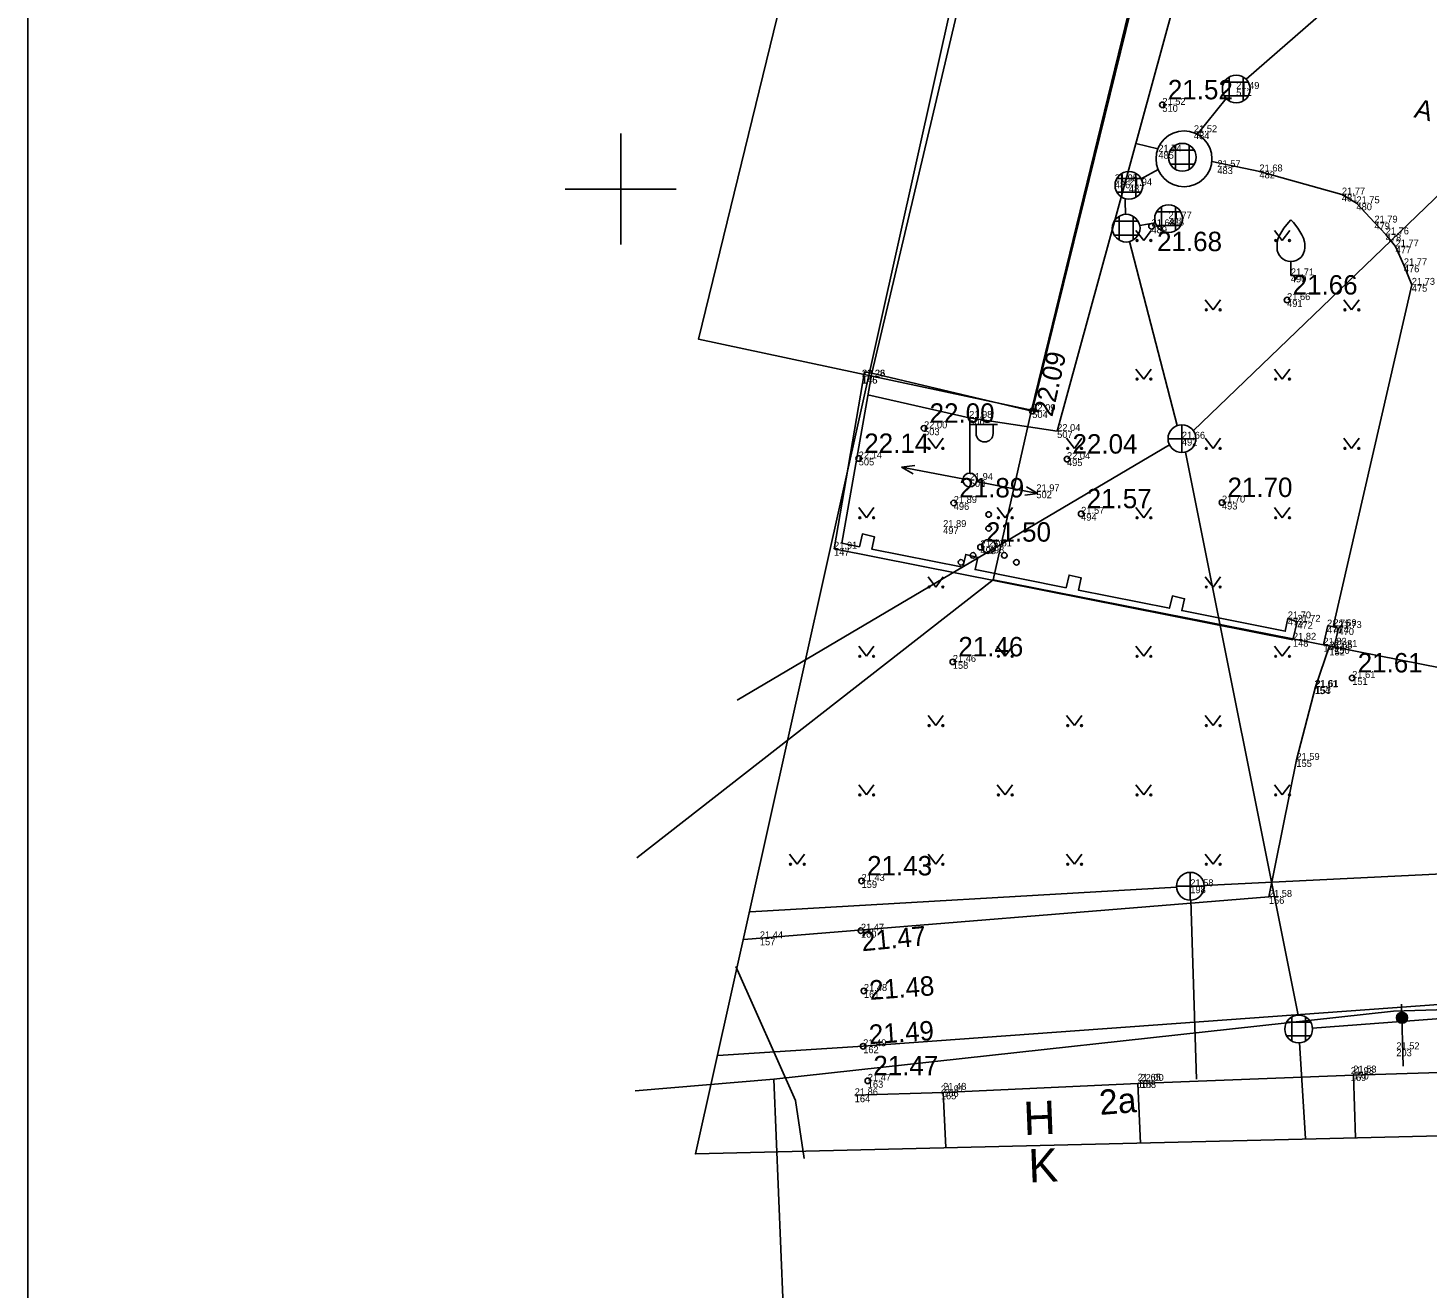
# Model space of a CAD drawing. Extents: x 714279 to 714471, y 6589851 to 6590083.
# Drawn here: x 714278.6 to 714329.1, y 6589960.4 to 6590005.8 of the extents above; entities that cross this region are included whole.
import ezdxf

# ---------------------------------------------------------------- set-up
doc = ezdxf.new("R2010")
doc.units = 0
for name, color, linetype in [('AED', 7, 'Continuous'), ('DKAEV', 7, 'Continuous'), ('DTRASS', 7, 'Continuous'), ('HALJASTUS', 7, 'Continuous'), ('HOONE', 7, 'Continuous'), ('KKAEV', 7, 'Continuous'), ('KORGUS', 7, 'Continuous'), ('KTRASS', 7, 'Continuous'), ('MOOTKORG', 7, 'Continuous'), ('MOOTMPUNKT', 7, 'Continuous'), ('MOOTPIIR', 7, 'Continuous'), ('MPKAABEL', 7, 'Continuous'), ('MPOHULIIN', 7, 'Continuous'), ('PIIR', 7, 'Continuous'), ('POST', 7, 'Continuous'), ('PUU', 7, 'Continuous'), ('RAJATISEDET', 7, 'Continuous'), ('SIOHULIIN', 7, 'Continuous'), ('SKKAEV', 7, 'Continuous'), ('SKTRASS', 7, 'Continuous'), ('TEE', 7, 'Continuous'), ('VORK', 7, 'Continuous'), ('VORMISTUS', 7, 'Continuous')]:
    doc.layers.add(name, color=color, linetype=linetype)

# ---------------------------------------------------------------- blocks, each defined once
blk = doc.blocks.new('RING02')
at = {"layer": 'KORGUS'}
blk.add_circle((0, 0), 0.2, dxfattribs=at)
blk = doc.blocks.new('RING02_2')
at = {"layer": 'KORGUS'}
blk.add_circle((0, 0), 0.2, dxfattribs=at)
blk = doc.blocks.new('RING02_1')
at = {"layer": 'KORGUS'}
blk.add_circle((0, 0), 0.2, dxfattribs=at)
blk = doc.blocks.new('KAKAEV')
at = {"layer": 'KKAEV'}
for p, q in [((-1, 0), (1, 0)), ((0, -1), (0, 1))]:
    blk.add_line(p, q, dxfattribs=at)
blk.add_circle((0, 0), 1, dxfattribs=at)
blk = doc.blocks.new('VILJA1')
at = {"layer": 'PUU'}
for p, q in [((0, 0), (0, 1)), ((0.8, 0), (0, 0))]:
    blk.add_line(p, q, dxfattribs=at)
for points in [[(-1, 2), (-1, 2.3), (-0.98, 2.43), (-0.91, 2.69), (-0.79, 2.93), (-0.5, 3.4), (-0.18, 3.81), (0, 4)], [(1, 2), (1, 2.3), (0.98, 2.43), (0.91, 2.69), (0.79, 2.93), (0.5, 3.4), (0.18, 3.81), (0, 4)]]:
    blk.add_lwpolyline(points, dxfattribs=at)
blk.add_arc((0, 2), 1, 180, 0, dxfattribs=at)
blk = doc.blocks.new('VQSA')
at = {"layer": 'HALJASTUS'}
for centre, radius in [((0, 2.3), 0.2), ((0, 1.3), 0.2), ((0, 0), 0.5), ((-2, -1.15), 0.2), ((-1.13, -0.65), 0.2), ((1.13, -0.65), 0.2), ((2, -1.15), 0.2)]:
    blk.add_circle(centre, radius, dxfattribs=at)
blk = doc.blocks.new('BEPOST')
at = {"layer": 'POST'}
for radius in [0.5, 0.0467]:
    blk.add_circle((0, 0), radius, dxfattribs=at)
blk = doc.blocks.new('POINT_DISPLAY')
blk.add_line((0, 0), (0, 0))
blk = doc.blocks.new('VAPOST')
at = {"layer": 'POST'}
for p, q in [((0, 0.5), (0, 4.5)), ((0, 4), (2, 4)), ((0.45, 3.36), (0.45, 4)), ((1.68, 3.36), (1.68, 4))]:
    blk.add_line(p, q, dxfattribs=at)
blk.add_arc((1.07, 3.36), 0.613, 180, 0, dxfattribs=at)
blk.add_blockref('POINT_DISPLAY', (0, 0), dxfattribs=at)
blk = doc.blocks.new('SISUUN')
at = {"layer": 'SIOHULIIN'}
blk.add_line((0.5, 0), (4.98, 0), dxfattribs=at)
for radius in [0.399, 0.38, 0.361, 0.342, 0.323, 0.304, 0.285, 0.266, 0.247, 0.228, 0.209, 0.191, 0.172, 0.153, 0.134, 0.115, 0.0959, 0.0769, 0.058, 0.0391, 0.0201, 0.00122]:
    blk.add_circle((3.99, 0), radius, dxfattribs=at)
blk.add_blockref('POINT_DISPLAY', (0, 0), dxfattribs=at)
blk = doc.blocks.new('MPSUUN')
at = {"layer": 'MPOHULIIN'}
for p, q in [((0.5, 0), (5, 0)), ((5, 0), (4.1, 0.3)), ((5, 0), (4.1, -0.3))]:
    blk.add_line(p, q, dxfattribs=at)
blk.add_blockref('POINT_DISPLAY', (0, 0), dxfattribs=at)
blk = doc.blocks.new('KAKAEV_1')
at = {"layer": 'SKKAEV'}
for p, q in [((-1, 0), (1, 0)), ((0, -1), (0, 1))]:
    blk.add_line(p, q, dxfattribs=at)
blk.add_circle((0, 0), 1, dxfattribs=at)
blk = doc.blocks.new('DRKAEV')
at = {"layer": 'DKAEV'}
for p, q in [((-0.87, 0.5), (0.87, 0.5)), ((-0.5, -0.87), (-0.5, 0.87)), ((0.5, 0.87), (0.5, -0.87)), ((0.87, -0.5), (-0.87, -0.5))]:
    blk.add_line(p, q, dxfattribs=at)
blk.add_circle((0, 0), 1, dxfattribs=at)
blk = doc.blocks.new('MURU_1')
at = {"layer": 'HALJASTUS'}
for p, q in [((-0.93, 1.21), (0, 0)), ((0, 0), (0.89, 1.21))]:
    blk.add_line(p, q, dxfattribs=at)
for centre in [(-0.8, 0), (0.86, 0)]:
    blk.add_circle(centre, 0.11, dxfattribs=at)

msp = doc.modelspace()

# ---------------------------------------------------------------- linework, layer by layer
at = {"layer": 'AED'}
for points in [[(714324.246, 6589983.744), (714324.403, 6589984.391), (714324.06, 6589984.514), (714323.969, 6589984.053), (714320.235, 6589984.794), (714320.337, 6589985.223), (714319.896, 6589985.328), (714319.79, 6589984.882), (714316.507, 6589985.534), (714316.612, 6589985.973), (714316.171, 6589986.078), (714316.062, 6589985.622), (714312.779, 6589986.273), (714312.885, 6589986.715), (714312.444, 6589986.82), (714312.334, 6589986.361), (714309.052, 6589987.012), (714309.157, 6589987.454), (714308.716, 6589987.559), (714308.607, 6589987.101), (714307.98, 6589987.225), (714309.058, 6589993.359), (714308.789, 6589993.405), (714307.695, 6589987.027), (714324.246, 6589983.744)], [(714325.888, 6589984.167), (714325.733, 6589983.485), (714325.349, 6589983.572), (714325.504, 6589984.254), (714325.888, 6589984.167)], [(714318.651, 6589967.739), (714326.425, 6589968.035)], [(714308.44, 6589967.315), (714311.635, 6589967.411)]]:
    msp.add_lwpolyline(points, dxfattribs=at)
at = {"layer": 'DTRASS'}
for points in [[(714328.331, 6590008.997), (714322.553, 6590003.965)], [(714321.838, 6590003.267), (714320.789, 6590001.966)], [(714319.39, 6590000.702), (714318.767, 6590000.375)], [(714318.193, 6589999.654), (714318.193, 6589999.561), (714318.205, 6589999.089)], [(714318.719, 6589998.692), (714319.281, 6589998.787)], [(714318.346, 6589998.104), (714320.074, 6589991.468)], [(714324.439, 6589970.203), (714320.365, 6589990.512)], [(714340.125, 6589970.88), (714324.95, 6589969.733)], [(714324.479, 6589969.204), (714324.695, 6589965.757)]]:
    msp.add_lwpolyline(points, dxfattribs=at)
at = {"layer": 'HOONE'}
for points in [[(714319.159, 6590036.112), (714325.33, 6590034.654), (714314.842, 6589991.992), (714309.058, 6589993.359), (714319.159, 6590036.112)], [(714326.496, 6589965.774), (714326.425, 6589968.035), (714339.231, 6589968.437), (714339.305, 6589966.095)], [(714311.727, 6589965.435), (714311.635, 6589967.411), (714318.651, 6589967.739), (714318.651, 6589967.739), (714318.752, 6589965.575)]]:
    msp.add_lwpolyline(points, dxfattribs=at)
at = {"layer": 'KORGUS'}
msp.add_circle((714314.842, 6589991.992), 0.1, dxfattribs=at)
at = {"layer": 'KTRASS'}
for points in [[(714321.04, 6589974.878), (714351.74, 6589976.38)], [(714304.668, 6589973.936), (714320.044, 6589974.823)], [(714320.559, 6589974.354), (714320.77, 6589967.891)]]:
    msp.add_lwpolyline(points, dxfattribs=at)
at = {"layer": 'MOOTPIIR'}
msp.add_lwpolyline([(714325.392, 6590064.148), (714418.405, 6590047.495), (714428.059, 6590039.059), (714392.952, 6589961.13), (714372.822, 6589966.903), (714302.696, 6589965.199), (714319.941, 6590042.637), (714325.392, 6590064.148)], dxfattribs=at)
at = {"layer": 'MPKAABEL'}
msp.add_lwpolyline([(714304.149, 6589971.964), (714306.307, 6589967.128), (714306.622, 6589965.036)], dxfattribs=at)
at = {"layer": 'PIIR'}
for points in [[(714331.191, 6590053.239), (714328.01, 6590040.642), (714325.217, 6590034.631), (714313.247, 6590037.362), (714302.809, 6589994.583), (714314.816, 6589992.023), (714325.215, 6590034.631)], [(714313.433, 6589985.9), (714378.228, 6589973.152), (714405.629, 6590034.791), (714332.408, 6590052.951), (714332.595, 6590052.951)], [(714314.816, 6589992.023), (714313.433, 6589985.9), (714300.583, 6589975.877)], [(714305.517, 6589967.896), (714327.878, 6589970.35), (714360.817, 6589971.365), (714377.13, 6589970.9), (714368.352, 6589950.974)], [(714300.523, 6589967.472), (714305.517, 6589967.896), (714305.864, 6589959.716), (714309.783, 6589950.981)]]:
    msp.add_lwpolyline(points, dxfattribs=at)
at = {"layer": 'RAJATISEDET'}
msp.add_circle((714320.316, 6590001.091), 1.008, dxfattribs=at)
at = {"layer": 'SKTRASS'}
for points in [[(714320.65, 6589991.283), (714354.787, 6590024.118)], [(714304.204, 6589981.56), (714319.79, 6589990.777)]]:
    msp.add_lwpolyline(points, dxfattribs=at)
at = {"layer": 'TEE'}
for points in [[(714308.915, 6589992.579), (714312.567, 6589991.748), (714315.741, 6589991.273), (714319.939, 6590006.608), (714326.841, 6590035.429), (714325.606, 6590035.884), (714319.931, 6590037.223), (714319.717, 6590036.149)], [(714319.374, 6590001.455), (714318.581, 6590001.648)], [(714323.053, 6590000.632), (714321.321, 6590000.993)], [(714325.7, 6589984.21), (714328.532, 6589996.547), (714328.246, 6589997.25), (714327.948, 6589997.931), (714327.592, 6589998.366), (714327.184, 6589998.792), (714326.536, 6589999.487), (714326.012, 6589999.804), (714323.037, 6590000.636)], [(714325.567, 6589983.523), (714325.055, 6589982.044)], [(714325.055, 6589982.044), (714324.371, 6589979.409), (714323.377, 6589974.469), (714304.436, 6589972.928)], [(714329.664, 6589970.604), (714308.745, 6589969.083), (714303.506, 6589968.747)]]:
    msp.add_lwpolyline(points, dxfattribs=at)
at = {"layer": 'VORK'}
for p, q in [((714300, 6590002), (714300, 6589998)), ((714298, 6590000), (714302, 6590000))]:
    msp.add_line(p, q, dxfattribs=at)
at = {"layer": 'VORMISTUS'}
msp.add_lwpolyline([(714471.122, 6589929.143), (714278.622, 6589929.143), (714278.622, 6590071.643), (714471.122, 6590071.643), (714471.122, 6589929.143)], dxfattribs=at)

# ---------------------------------------------------------------- block references
at = {"layer": 'DKAEV', "xscale": 0.5, "yscale": 0.5}
for p in [(714322.199, 6590003.611), (714320.258, 6590001.148), (714318.328, 6590000.136), (714319.759, 6589998.933), (714318.229, 6589998.59), (714324.45, 6589969.704)]:
    msp.add_blockref('DRKAEV', p, dxfattribs=at)
at = {"layer": 'HALJASTUS'}
for name, p, xscale, yscale in [('MURU_1', (714318.862, 6589998.147), 0.3, 0.3), ('MURU_1', (714323.862, 6589998.147), 0.3, 0.3), ('MURU_1', (714321.362, 6589995.647), 0.3, 0.3), ('MURU_1', (714326.362, 6589995.647), 0.3, 0.3), ('MURU_1', (714318.862, 6589993.147), 0.3, 0.3), ('MURU_1', (714323.862, 6589993.147), 0.3, 0.3), ('MURU_1', (714311.362, 6589990.647), 0.3, 0.3), ('MURU_1', (714316.362, 6589990.647), 0.3, 0.3), ('MURU_1', (714321.362, 6589990.647), 0.3, 0.3), ('MURU_1', (714326.362, 6589990.647), 0.3, 0.3), ('MURU_1', (714308.862, 6589988.147), 0.3, 0.3), ('VQSA', (714313.272, 6589987.113), 0.5, 0.5), ('MURU_1', (714313.862, 6589988.147), 0.3, 0.3), ('MURU_1', (714318.862, 6589988.147), 0.3, 0.3), ('MURU_1', (714323.862, 6589988.147), 0.3, 0.3), ('MURU_1', (714311.362, 6589985.647), 0.3, 0.3), ('MURU_1', (714321.362, 6589985.647), 0.3, 0.3), ('MURU_1', (714308.862, 6589983.147), 0.3, 0.3), ('MURU_1', (714313.862, 6589983.147), 0.3, 0.3), ('MURU_1', (714318.862, 6589983.147), 0.3, 0.3), ('MURU_1', (714323.862, 6589983.147), 0.3, 0.3), ('MURU_1', (714311.362, 6589980.647), 0.3, 0.3), ('MURU_1', (714316.362, 6589980.647), 0.3, 0.3), ('MURU_1', (714321.362, 6589980.647), 0.3, 0.3), ('MURU_1', (714308.862, 6589978.147), 0.3, 0.3), ('MURU_1', (714313.862, 6589978.147), 0.3, 0.3), ('MURU_1', (714318.862, 6589978.147), 0.3, 0.3), ('MURU_1', (714323.862, 6589978.147), 0.3, 0.3), ('MURU_1', (714306.362, 6589975.647), 0.3, 0.3), ('MURU_1', (714311.362, 6589975.647), 0.3, 0.3), ('MURU_1', (714316.362, 6589975.647), 0.3, 0.3), ('MURU_1', (714321.362, 6589975.647), 0.3, 0.3)]:
    msp.add_blockref(name, p, dxfattribs=dict(at, xscale=xscale, yscale=yscale))
at = {"layer": 'KKAEV', "xscale": 0.5, "yscale": 0.5}
for p in [(714320.24, 6589990.996), (714320.543, 6589974.854)]:
    msp.add_blockref('KAKAEV', p, dxfattribs=at)
at = {"layer": 'KORGUS', "xscale": 0.5, "yscale": 0.5}
for name, p in [('RING02', (714319.535, 6590003.037)), ('RING02_2', (714319.145, 6589998.658)), ('RING02', (714324.034, 6589995.996)), ('RING02', (714310.941, 6589991.372)), ('RING02_1', (714308.584, 6589990.283)), ('RING02', (714316.096, 6589990.259)), ('RING02', (714312.011, 6589988.678)), ('RING02', (714321.685, 6589988.693)), ('RING02', (714316.607, 6589988.288)), ('RING02', (714312.975, 6589987.083)), ('RING02', (714311.977, 6589982.946)), ('RING02', (714326.382, 6589982.366)), ('RING02', (714308.687, 6589975.045)), ('RING02_2', (714308.664, 6589973.251)), ('RING02_1', (714308.771, 6589971.078)), ('RING02_2', (714308.745, 6589969.083)), ('RING02', (714308.911, 6589967.836))]:
    msp.add_blockref(name, p, dxfattribs=at)
at = {"layer": 'MPOHULIIN', "xscale": 0.5, "yscale": 0.5}
for rotation in [169.47487191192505, -11.231766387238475]:
    msp.add_blockref('MPSUUN', (714312.59, 6589989.507), dxfattribs=dict(at, rotation=rotation))
at = {"layer": 'POST', "xscale": 0.5, "yscale": 0.5}
for name, p in [('VAPOST', (714312.59, 6589989.507)), ('BEPOST', (714312.589, 6589989.507))]:
    msp.add_blockref(name, p, dxfattribs=at)
at = {"layer": 'PUU', "xscale": 0.5, "yscale": 0.5}
msp.add_blockref('VILJA1', (714324.171, 6589996.886), dxfattribs=at)
at = {"layer": 'SIOHULIIN', "xscale": 0.49999999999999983, "yscale": 0.4999999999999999, "rotation": 91.40279018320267}
msp.add_blockref('SISUUN', (714328.226, 6589968.115), dxfattribs=at)
at = {"layer": 'SKKAEV', "xscale": 0.5, "yscale": 0.5}
msp.add_blockref('KAKAEV_1', (714320.24, 6589990.996), dxfattribs=at)

# ---------------------------------------------------------------- texts
at = {"layer": 'HOONE'}
for s, height, rotation, p in [('2a', 0.9, 4.4689, (714317.293, 6589966.604)), ('H', 1.2, 2.2992, (714314.547, 6589965.878)), ('K', 1.2, 2.2992, (714314.727, 6589964.166))]:
    msp.add_text(s, height=height, rotation=rotation, dxfattribs=at).set_placement(p)
at = {"layer": 'KORGUS'}
for s, p in [('21.52', (714319.735, 6590003.237)), ('21.68', (714319.345, 6589997.761)), ('21.66', (714324.234, 6589996.196)), ('22.00', (714311.141, 6589991.572)), ('22.14', (714308.784, 6589990.483)), ('22.04', (714316.296, 6589990.459)), ('21.89', (714312.211, 6589988.878)), ('21.70', (714321.885, 6589988.893)), ('21.57', (714316.807, 6589988.488)), ('21.50', (714313.175, 6589987.283)), ('21.46', (714312.177, 6589983.146)), ('21.61', (714326.582, 6589982.566)), ('21.43', (714308.887, 6589975.245)), ('21.47', (714309.111, 6589968.036))]:
    msp.add_text(s, height=0.7, dxfattribs=at).set_placement(p)
for s, rotation, p in [('22.09', 77.5872, (714315.567, 6589991.761)), ('21.47', 5.5012, (714308.711, 6589972.506)), ('21.48', 4.2186, (714308.996, 6589970.753)), ('21.49', 3.7117, (714308.978, 6589969.157))]:
    msp.add_text(s, height=0.7, rotation=rotation, dxfattribs=at).set_placement(p)
at = {"layer": 'MOOTKORG'}
for s, p in [('21.49', (714322.199, 6590003.611)), ('21.52', (714319.535, 6590003.037)), ('21.52', (714320.674, 6590002.051)), ('21.74', (714319.39, 6590001.346)), ('21.57', (714321.519, 6590000.791)), ('21.68', (714323.037, 6590000.636)), ('21.95', (714317.819, 6590000.28)), ('21.94', (714318.328, 6590000.136)), ('21.77', (714326.012, 6589999.804)), ('21.75', (714326.536, 6589999.487)), ('21.68', (714319.145, 6589998.658)), ('21.77', (714319.759, 6589998.933)), ('21.79', (714327.184, 6589998.792)), ('21.76', (714327.592, 6589998.366)), ('21.77', (714327.948, 6589997.931)), ('21.77', (714328.246, 6589997.25)), ('21.71', (714324.171, 6589996.886)), ('21.73', (714328.532, 6589996.547)), ('21.66', (714324.034, 6589995.996)), ('22.28', (714308.696, 6589993.232)), ('22.26', (714308.707, 6589993.236)), ('22.09', (714314.842, 6589991.992)), ('21.98', (714312.567, 6589991.748)), ('22.00', (714310.941, 6589991.372)), ('22.04', (714315.741, 6589991.273)), ('21.66', (714320.24, 6589990.996)), ('22.14', (714308.584, 6589990.283)), ('22.04', (714316.096, 6589990.259)), ('21.94', (714312.589, 6589989.507)), ('21.94', (714312.59, 6589989.507)), ('21.97', (714314.991, 6589989.1)), ('21.89', (714312.011, 6589988.678)), ('21.70', (714321.685, 6589988.693)), ('21.57', (714316.607, 6589988.288)), ('21.89', (714311.629, 6589987.809)), ('21.91', (714307.695, 6589987.027)), ('21.50', (714312.975, 6589987.083)), ('21.51', (714313.272, 6589987.113)), ('21.70', (714324.06, 6589984.514)), ('21.72', (714324.403, 6589984.391)), ('21.75', (714325.477, 6589984.221)), ('21.69', (714325.705, 6589984.234)), ('21.73', (714325.888, 6589984.167)), ('21.82', (714324.246, 6589983.744)), ('21.83', (714325.347, 6589983.563)), ('21.65', (714325.56, 6589983.428)), ('21.81', (714325.733, 6589983.485)), ('21.46', (714311.977, 6589982.946)), ('21.61', (714325.023, 6589982.033)), ('21.61', (714325.055, 6589982.044)), ('21.61', (714326.382, 6589982.366)), ('21.59', (714324.371, 6589979.409)), ('21.43', (714308.687, 6589975.045)), ('21.58', (714320.543, 6589974.854)), ('21.58', (714323.377, 6589974.469)), ('21.44', (714305.018, 6589972.975)), ('21.47', (714308.664, 6589973.251)), ('21.48', (714308.771, 6589971.078)), ('21.49', (714308.745, 6589969.083)), ('21.52', (714327.974, 6589968.972)), ('21.47', (714308.911, 6589967.836)), ('21.65', (714318.646, 6589967.839)), ('22.00', (714318.748, 6589967.83)), ('21.93', (714326.331, 6589968.081)), ('21.53', (714326.422, 6589968.135)), ('21.86', (714308.44, 6589967.315)), ('21.91', (714311.546, 6589967.419)), ('21.48', (714311.63, 6589967.511))]:
    msp.add_text(s, height=0.25, dxfattribs=at).set_placement(p)
at = {"layer": 'MOOTMPUNKT'}
for s, p in [('511', (714322.199, 6590003.361)), ('510', (714319.535, 6590002.787)), ('484', (714320.674, 6590001.801)), ('485', (714319.39, 6590001.096)), ('483', (714321.519, 6590000.541)), ('482', (714323.037, 6590000.386)), ('486', (714317.819, 6590000.03)), ('487', (714318.328, 6589999.886)), ('481', (714326.012, 6589999.554)), ('480', (714326.536, 6589999.237)), ('488', (714319.759, 6589998.683)), ('489', (714319.145, 6589998.408)), ('479', (714327.184, 6589998.542)), ('478', (714327.592, 6589998.116)), ('477', (714327.948, 6589997.681)), ('490', (714324.171, 6589996.636)), ('476', (714328.246, 6589997)), ('475', (714328.532, 6589996.297)), ('491', (714324.034, 6589995.746)), ('146', (714308.696, 6589992.982)), ('145', (714308.707, 6589992.986)), ('506', (714312.567, 6589991.498)), ('504', (714314.842, 6589991.742)), ('503', (714310.941, 6589991.122)), ('507', (714315.741, 6589991.023)), ('492', (714320.24, 6589990.746)), ('505', (714308.584, 6589990.033)), ('495', (714316.096, 6589990.009)), ('500', (714312.589, 6589989.257)), ('501', (714312.59, 6589989.257)), ('502', (714314.991, 6589988.85)), ('496', (714312.011, 6589988.428)), ('494', (714316.607, 6589988.038)), ('493', (714321.685, 6589988.443)), ('497', (714311.629, 6589987.559)), ('147', (714307.695, 6589986.777)), ('499', (714312.975, 6589986.833)), ('498', (714313.272, 6589986.863)), ('473', (714324.06, 6589984.264)), ('472', (714324.403, 6589984.141)), ('471', (714325.477, 6589983.971)), ('474', (714325.705, 6589983.984)), ('470', (714325.888, 6589983.917)), ('148', (714324.246, 6589983.494)), ('149', (714325.347, 6589983.313)), ('152', (714325.56, 6589983.178)), ('150', (714325.733, 6589983.235)), ('158', (714311.977, 6589982.696)), ('151', (714326.382, 6589982.116)), ('154', (714325.023, 6589981.783)), ('153', (714325.055, 6589981.794)), ('155', (714324.371, 6589979.159)), ('159', (714308.687, 6589974.795)), ('198', (714320.543, 6589974.604)), ('156', (714323.377, 6589974.219)), ('160', (714308.664, 6589973.001)), ('157', (714305.018, 6589972.725)), ('161', (714308.771, 6589970.828)), ('162', (714308.745, 6589968.833)), ('203', (714327.974, 6589968.722)), ('169', (714326.331, 6589967.831)), ('170', (714326.422, 6589967.885)), ('163', (714308.911, 6589967.586)), ('166', (714311.63, 6589967.261)), ('167', (714318.646, 6589967.589)), ('168', (714318.748, 6589967.58)), ('164', (714308.44, 6589967.065)), ('165', (714311.546, 6589967.169))]:
    msp.add_text(s, height=0.25, dxfattribs=at).set_placement(p)
at = {"layer": 'TEE'}
msp.add_text('A', height=0.7, rotation=345.7136, dxfattribs=at).set_placement((714328.583, 6590002.596))

doc.saveas('drawing.dxf')
